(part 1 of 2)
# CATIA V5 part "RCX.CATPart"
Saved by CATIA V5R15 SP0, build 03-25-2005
Part number: Part1
Material "DS Yellow": density 7860 kg/m3, Young's modulus 2e+11 Pa, Poisson ratio 0.266
Material "Black": density 7860 kg/m3, Young's modulus 2e+11 Pa, Poisson ratio 0.266
Material "Purple Grey": density 7860 kg/m3, Young's modulus 2e+11 Pa, Poisson ratio 0.266
Material "Fire Red": density 7860 kg/m3, Young's modulus 2e+11 Pa, Poisson ratio 0.266
Material "Black": density 7860 kg/m3, Young's modulus 2e+11 Pa, Poisson ratio 0.266
Material "Silver Grey": density 7860 kg/m3, Young's modulus 2e+11 Pa, Poisson ratio 0.266
Material "DS Green": density 7860 kg/m3, Young's modulus 2e+11 Pa, Poisson ratio 0.266
Material "Dark Grey": density 7860 kg/m3, Young's modulus 2e+11 Pa, Poisson ratio 0.266
Material "Bathroom Floor": density 2770 kg/m3, Young's modulus 6e+10 Pa, Poisson ratio 0.3
Material "Plastic": density 1200 kg/m3, Young's modulus 2.2e+09 Pa, Poisson ratio 0.38, thermal expansion 6.84e-05 1/K
Bounding box of the stored display mesh (mm): x -320 to 320, y -3 to 960, z 0 to 397.2
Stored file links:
  E:\#01 CATIA Lecture Materials\#06 DMU\#11 DMU Page01 KIN EX11\RCX.CATPart
  C:\Program Files\Dassault Systemes\B20\win_b64\startup\materials\Catalog.CATMaterial
  C:\Program Files\Dassault Systemes\B20\win_b64\startup\materials\yellow_env_512x512.jpg
  C:\Program Files\Dassault Systemes\B20\win_b64\startup\materials\green_env_512x512.jpg
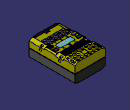
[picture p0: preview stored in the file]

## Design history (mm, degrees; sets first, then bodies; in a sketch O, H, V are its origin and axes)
Body1 (main body), material "DS Yellow"
  Sketch1 on xy-plane, origin (0, 0, 0), H (1, 0, 0), V (0, 1, 0)
    point P1 (320, 0)
    line L1 (320, 0) -> (320, 960)
    line L2 (320, 960) -> (-320, 960)
    line L3 (-320, 960) -> (-320, 0)
    point P4 (-320, 0)
    line L4 (-320, 0) -> (320, 0)
    length L1 = 960
    distance L1 L3 = 640
    coincidence: P1 H, P4 H
    vertical: L1 V, L3 V
    horizontal: L2 H, L4 H
    symmetry: L1 L3 V
  Pad1: profile Sketch1, direction (0, 0, 1), length 380
  Sketch2 on face of Pad1 from Sketch1.L4, origin (0, 0, 0), H (1, 0, 0), V (0, 0, 1)
    point P1 (245, 380)
    line L1 (245, 380) -> (320, 380)
    point P2 (320, 380)
    line L2 (320, 380) -> (320, 345)
    point P3 (320, 345)
    line L3 (320, 345) -> (245, 380)
    reference projected line E1 (320, 0) -> (320, 380) from edge [face of Pad1 from Sketch1.L1 | face of Pad1 from Sketch1.L4]
    reference projected line E2 (-320, 380) -> (320, 380) from edge [face of Pad1 from Sketch1.L4 | end face of Pad1]
    point P4 (-245, 380)
    point P5 (-320, 380)
    point P6 (-320, 345)
    line L4 (-245, 380) -> (-320, 380)
    line L5 (-320, 380) -> (-320, 345)
    line L6 (-320, 345) -> (-245, 380)
    length L2 = 35
    length L1 = 75
    horizontal: L1 H
    vertical: L2 V
    coincidence: L2 E1, L1 E2
    symmetry: P1 P4 V, P2 P5 V, P3 P6 V, L1 L4 V, L2 L5 V, L3 L6 V
  Pocket1: profile Sketch2, direction (0, 1, 0), through (limit type 6)
  Sketch3 on face of Pad1 from Sketch1.L4, origin (0, 0, 0), H (1, 0, 0), V (0, 0, 1)
    line L1 (-320, 380) -> (320, 380)
    line L2 (320, 380) -> (320, 350)
    line L3 (320, 350) -> (-320, 350)
    line L4 (-320, 350) -> (-320, 380)
    reference projected line E1 (-320, 380) -> (320, 380) from edge [face of Pad1 from Sketch1.L4 | end face of Pad1]
    reference projected line E2 (320, 0) -> (320, 380) from edge [face of Pad1 from Sketch1.L1 | face of Pad1 from Sketch1.L4]
    reference projected line E3 (-320, 0) -> (-320, 380) from edge [face of Pad1 from Sketch1.L4 | face of Pad1 from Sketch1.L3]
    distance L3 L1 = 30
    horizontal: L1 H, L3 H
    vertical: L2 V, L4 V
    coincidence: L1 E1, L2 E2, L4 E3
  Pocket2: profile Sketch3, direction (0, 1, 0), length 720
  Sketch4 on face of Pad1 from Sketch1.L4, origin (0, 0, 0), H (1, 0, 0), V (0, 0, 1)
    point P1 (245, 350)
    line L1 (245, 350) -> (320, 350)
    point P2 (320, 350)
    line L2 (320, 350) -> (320, 315)
    point P3 (320, 315)
    line L3 (320, 315) -> (245, 350)
    reference projected line E1 (-309.2857, 350) -> (309.2857, 350) from edge [face of Pad1 from Sketch1.L4 | face of Pocket2 from Sketch3.L3]
    reference projected line E2 (320, 0) -> (320, 380) from edge [face of Pad1 from Sketch1.L1 | face of Pad1 from Sketch1.L4]
    point P4 (-245, 350)
    point P5 (-320, 350)
    point P6 (-320, 315)
    line L4 (-245, 350) -> (-320, 350)
    line L5 (-320, 350) -> (-320, 315)
    line L6 (-320, 315) -> (-245, 350)
    length L2 = 35
    length L1 = 75
    horizontal: L1 H
    vertical: L2 V
    coincidence: L1 E1, L2 E2
    symmetry: P1 P4 V, P2 P5 V, P3 P6 V, L1 L4 V, L2 L5 V, L3 L6 V
  Pocket3: profile Sketch4, direction (0, 1, 0), length 320
  Sketch5 on face of Pad1 from Sketch1.L4, origin (0, 0, 0), H (1, 0, 0), V (0, 0, 1)
    point P1 (245, 350)
    line L1 (245, 350) -> (320, 350)
    point P2 (320, 350)
    line L2 (320, 350) -> (320, 315)
    point P3 (320, 315)
    line L3 (320, 315) -> (245, 350)
    reference projected line E1 (-309.2857, 350) -> (309.2857, 350) from edge [face of Pad1 from Sketch1.L4 | face of Pocket2 from Sketch3.L3]
    reference projected line E2 (320, 0) -> (320, 380) from edge [face of Pad1 from Sketch1.L1 | face of Pad1 from Sketch1.L4]
    point P4 (-245, 350)
    point P5 (-320, 350)
    point P6 (-320, 315)
    line L4 (-245, 350) -> (-320, 350)
    line L5 (-320, 350) -> (-320, 315)
    line L6 (-320, 315) -> (-245, 350)
    length L2 = 35
    length L1 = 75
    horizontal: L1 H
    vertical: L2 V
    coincidence: L1 E1, L2 E2
    symmetry: P1 P4 V, P2 P5 V, P3 P6 V, L1 L4 V, L2 L5 V, L3 L6 V
  Pocket4: profile Sketch5, direction (0, 1, 0), length 720, opposite side length -550
  Sketch6 on end face of Pocket3, origin (0, 320, 0), H (1, 0, 0), V (0, 0, 1)
    point P1 (320, 335)
    line L1 (320, 335) -> (320, 350)
    point P2 (320, 350)
    line L2 (320, 350) -> (290, 350)
    point P3 (290, 350)
    line L3 (290, 350) -> (320, 335)
    reference projected line E1 (-245, 350) -> (-309.2857, 350) from edge [face of Pocket2 from Sketch3.L3 | end face of Pocket3]
    reference projected line E3 (320, 315) -> (320, 345) from edge [face of Pad1 from Sketch1.L1 | end face of Pocket3]
    point P4 (-320, 335)
    point P5 (-320, 350)
    point P6 (-290, 350)
    line L4 (-320, 335) -> (-320, 350)
    line L5 (-320, 350) -> (-290, 350)
    line L6 (-290, 350) -> (-320, 335)
    length L2 = 30
    length L1 = 15
    vertical: L1 V
    horizontal: L2 H
    coincidence: L2 E1, L1 E3
    symmetry: P1 P4 V, P2 P5 V, P3 P6 V, L1 L4 V, L2 L5 V, L3 L6 V
  Pocket5: profile Sketch6, direction (0, 1, 0), length 230
  Sketch7 on face of Pocket2 from Sketch3.L3, origin (0, 0, 350), H (1, 0, 0), V (0, 1, 0)
    line L1 (-237, 720) -> (237, 720)
    line L2 (237, 720) -> (237, 562)
    line L3 (237, 562) -> (-237, 562)
    line L4 (-237, 562) -> (-237, 720)
    reference projected line E1 (320, 720) -> (-320, 720) from edge [face of Pocket2 from Sketch3.L3 | face of Pocket4]
    line L5 (237, 162) -> (-237, 162)
    line L6 (237, 320) -> (237, 162)
    line L7 (-237, 320) -> (237, 320)
    line L8 (-237, 162) -> (-237, 320)
    reference projected line E2 (-245, 320) -> (-309.2857, 320) from edge [face of Pocket2 from Sketch3.L3 | end face of Pocket3]
    length L2 = 158
    distance L2 L4 = 474
    distance L5 L7 = 158
    distance L6 L8 = 474
    horizontal: L1 H, L3 H
    vertical: L2 V, L4 V
    coincidence: L1 E1, L7 E2
    symmetry: L2 L4 V, L6 L8 V
  Pocket6: profile Sketch7, direction (0, 0, -1), length 32
  Sketch8 on face of Pad1 from Sketch1.L2, origin (0, 960, 0), H (-1, 0, 0), V (0, 0, 1)
    point P1 (-320, 190)
    line L1 (-320, 190) -> (320, 190)
    point P2 (320, 190)
    reference projected line E1 (-320, 380) -> (320, 380) from edge [face of Pad1 from Sketch1.L2 | end face of Pad1]
    reference projected line E2 (320, 0) -> (320, 380) from edge [face of Pad1 from Sketch1.L3 | face of Pad1 from Sketch1.L2]
    reference projected line E3 (-320, 0) -> (-320, 380) from edge [face of Pad1 from Sketch1.L2 | face of Pad1 from Sketch1.L1]
    distance L1 E1 = 190
    horizontal: L1 H
    coincidence: P2 E2, P1 E3
  Pocket7: profile Sketch8, direction (0, -1, 0), length 5, thin wall 5, second thickness 5
  Sketch9 on face of Pad1 from Sketch1.L3, origin (-320, 0, 0), H (0, -1, 0), V (0, 0, 1)
    point P1 (-960, 190)
    line L1 (-960, 190) -> (0, 190)
    point P2 (0, 190)
    reference projected line E1 (-960, 0) -> (-960, 380) from edge [face of Pad1 from Sketch1.L3 | face of Pad1 from Sketch1.L2]
    reference projected line E2 (0, 380) -> (-960, 380) from edge [end face of Pad1 | face of Pocket1 from Sketch2.L6]
    reference projected line E3 (0, 0) -> (0, 380) from edge [face of Pad1 from Sketch1.L4 | face of Pad1 from Sketch1.L3]
    distance L1 E2 = 190
    horizontal: L1 H
    coincidence: P1 E1, P2 E3
  Pocket8: profile Sketch9, direction (1, 0, 0), length 5, thin wall 5, second thickness 5
  Sketch10 on face of Pad1 from Sketch1.L4, origin (0, 0, 0), H (1, 0, 0), V (0, 0, 1)
    point P1 (-320, 190)
    line L1 (-320, 190) -> (320, 190)
    point P2 (320, 190)
    reference projected line E1 (245, 380) -> (-245, 380) from edge [end face of Pad1 | face of Pocket4]
    reference projected line E2 (-320, 0) -> (-320, 380) from edge [face of Pad1 from Sketch1.L4 | face of Pad1 from Sketch1.L3]
    reference projected line E3 (320, 0) -> (320, 380) from edge [face of Pad1 from Sketch1.L1 | face of Pad1 from Sketch1.L4]
    distance E1 L1 = 190
    horizontal: L1 H
    coincidence: P1 E2, P2 E3
  Pocket9: profile Sketch10, direction (0, 1, 0), length 5, thin wall 5, second thickness 5
  Sketch11 on face of Pad1 from Sketch1.L1, origin (320, 0, 0), H (0, 1, 0), V (0, 0, 1)
    point P1 (0, 190)
    line L1 (0, 190) -> (960, 190)
    point P2 (960, 190)
    reference projected line E1 (960, 0) -> (960, 380) from edge [face of Pad1 from Sketch1.L2 | face of Pad1 from Sketch1.L1]
    reference projected line E2 (0, 0) -> (0, 380) from edge [face of Pad1 from Sketch1.L1 | face of Pad1 from Sketch1.L4]
    reference projected line E3 (0, 380) -> (960, 380) from edge [face of Pocket1 from Sketch2.L3 | end face of Pad1]
    distance L1 E3 = 190
    horizontal: L1 H
    coincidence: P2 E1, P1 E2
  Pocket10: profile Sketch11, direction (-1, 0, 0), length 5, thin wall 5, second thickness 5
  Sketch12 on face of Pad1 from Sketch1.L4, origin (0, 0, 0), H (1, 0, 0), V (0, 0, 1)
    point P1 (320, 0)
    line L1 (320, 0) -> (-320, 0)
    line L2 (-320, 0) -> (-320, 185)
    line L3 (-320, 185) -> (320, 185)
    line L4 (320, 185) -> (320, 0)
    reference projected line E1 (-320, 185) -> (-315, 185) from edge [face of Pad1 from Sketch1.L4 | face of Pocket10]
    reference projected line E2 (320, 0) -> (320, 380) from edge [face of Pad1 from Sketch1.L1 | face of Pad1 from Sketch1.L4]
    reference projected line E3 (-320, 0) -> (-320, 380) from edge [face of Pad1 from Sketch1.L4 | face of Pad1 from Sketch1.L3]
    coincidence: P1 H, E1 L3, E2 L4, L2 E3
    horizontal: L1 H, L3 H
    vertical: L2 V, L4 V
  Pocket11: profile Sketch12, direction (0, 1, 0), through (limit type 6)
  Sketch13 on face of Pocket2 from Sketch3.L3, origin (0, 0, 350), H (1, 0, 0), V (0, 1, 0)
    line L1 (-160, 485) -> (-160, 385)
    arc A1 centre (0, 1660) radius 1285 from (-160, 385) to (160, 385) ccw
    point P4 (0, 375)
    line L2 (160, 385) -> (160, 485)
    arc A2 centre (0, -790) radius 1285 from (160, 485) to (-160, 485) ccw
    point P8 (0, 495)
    axis line L3 (534.9151, 435) -> (-283.043, 435)
    reference projected line E1 (-245, 320) -> (-309.2857, 320) from edge [face of Pocket2 from Sketch3.L3 | end face of Pocket3]
    length L2 = 100
    length L1 = 100
    distance L2 L1 = 320
    distance L3 E1 = 115
    distance A2 A1 = 120
    vertical: L1 V, L2 V
    coincidence: A1 P4, P4 V, A2 P8, P8 V
    symmetry: L1 L2 V, A1 A2 L3
    horizontal: L3 H
  Pocket12: profile Sketch13, direction (0, 0, -1), length 30
  Sketch14 on face of Pocket2 from Sketch3.L3, origin (0, 0, 350), H (1, 0, 0), V (0, 1, 0)
    point P1 (200, 507.5)
    line L1 (200, 507.5) -> (200, 472.5)
    point P2 (200, 472.5)
    arc A1 centre (240, 630) radius 162.5 from (200, 472.5) to (280, 472.5) ccw
    point P3 (240, 630)
    point P4 (280, 472.5)
    line L2 (280, 472.5) -> (280, 507.5)
    point P5 (280, 507.5)
    arc A2 centre (240, 350) radius 162.5 from (280, 507.5) to (200, 507.5) ccw
    point P6 (240, 350)
    construction line L3 (240, 533.7605) -> (240, 386.1992)
    point P7 (240, 533.7605)
    reference projected line E1 (320, 320) -> (320, 550) from edge [face of Pad1 from Sketch1.L1 | face of Pocket5 from Sketch6.L3]
    construction line L4 (152.5705, 490) -> (327.5235, 490)
    point P9 (152.5705, 490)
    point P10 (327.5235, 490)
    reference projected line E2 (-245, 550) -> (-309.2857, 550) from edge [start face of Pocket4 | face of Pocket2 from Sketch3.L3]
    construction line L5 (479.259, 435) -> (35.5084, 435)
    reference projected line E4 (-245, 320) -> (-309.2857, 320) from edge [face of Pocket2 from Sketch3.L3 | end face of Pocket3]
    point P13 (200, 362.5)
    point P14 (200, 397.5)
    point P15 (280, 397.5)
    point P16 (280, 362.5)
    point P17 (240, 336.2395)
    point P18 (152.5705, 380)
    point P19 (327.5235, 380)
    construction line L6 (152.5705, 380) -> (327.5235, 380)
    line L7 (200, 362.5) -> (200, 397.5)
    arc A3 centre (240, 240) radius 162.5 from (200, 397.5) to (280, 397.5) cw
    line L8 (280, 397.5) -> (280, 362.5)
    point P21 (240, 520)
    arc A4 centre (240, 520) radius 162.5 from (280, 362.5) to (200, 362.5) cw
    point P22 (-200, 507.5)
    point P23 (-200, 472.5)
    point P24 (-280, 472.5)
    point P25 (-280, 507.5)
    point P26 (-240, 533.7605)
    point P27 (-327.5235, 490)
    point P28 (-240, 520)
    line L9 (-200, 507.5) -> (-200, 472.5)
    arc A5 centre (-240, 630) radius 162.5 from (-200, 472.5) to (-280, 472.5) cw
    line L10 (-280, 472.5) -> (-280, 507.5)
    arc A6 centre (-240, 350) radius 162.5 from (-280, 507.5) to (-200, 507.5) cw
    arc A7 centre (-240, 520) radius 162.5 from (-280, 362.5) to (-200, 362.5) ccw
    arc A8 centre (-240, 240) radius 162.5 from (-200, 397.5) to (-280, 397.5) ccw
    line L11 (-200, 362.5) -> (-200, 397.5)
    line L12 (-280, 397.5) -> (-280, 362.5)
    construction line L13 (-240, 419.4533) -> (-240, 336.2395)
    reference projected line E6 (-320, 0) -> (-320, 320) from edge [face of Pocket3 from Sketch4.L6 | face of Pad1 from Sketch1.L3]
    axis line L14 (-343.1113, 380) -> (-157.5, 380)
    point P39 (-157.5, 380)
    distance L3 E1 = 80
    distance L2 L1 = 80
    distance A2 A1 = 45
    distance L4 E2 = 60
    length L2 = 35
    distance L5 E4 = 115
    distance L12 L11 = 80
    distance A8 A7 = 45
    distance L13 E6 = 80
    length L12 = 35
    length L11 = 35
    vertical: L1 V, L2 V, L3 V, L13 V
    coincidence: P3 L3, P6 L3, P39 A7
    symmetry: L2 L1 L3, A1 A2 L4, P1 P13 L5, P2 P14 L5, P4 P15 L5, P5 P16 L5, P7 P17 L5, P9 P18 L5, P10 P19 L5, L4 L6 L5, L1 L7 L5, A1 A3 L5, L2 L8 L5, A2 A4 L5, P1 P22 V, P2 P23 V, P4 P24 V, P5 P25 V, P7 P26 V, P10 P27 V, P21 P28 V, L1 L9 V, A1 A5 V, L2 L10 V, A2 A6 V, A8 A7 L6, L12 L11 L13, A8 A7 L14
    horizontal: L4 H, L5 H, L14 H
  Pocket13: profile Sketch14, direction (0, 0, -1), length 30
  Sketch15 on face of Pocket2 from Sketch3.L3, origin (0, 0, 350), H (1, 0, 0), V (0, 1, 0)
    point P1 (237.5, 0)
    line L1 (237.5, 0) -> (237.5, 40)
    line L2 (237.5, 40) -> (40, 40)
    line L3 (40, 40) -> (40, 80)
    line L4 (40, 80) -> (-40, 80)
    line L5 (-40, 80) -> (-40, 40)
    point P6 (-40, 40)
    line L6 (-40, 40) -> (-237.5, 40)
    line L7 (-237.5, 40) -> (-237.5, 0)
    point P8 (-237.5, 0)
    line L8 (-237.5, 0) -> (237.5, 0)
    distance L3 L5 = 80
    distance L2 L8 = 40
    distance L4 L8 = 80
    distance L1 L7 = 475
    coincidence: P1 H, P6 L2, P8 H
    vertical: L1 V, L3 V, L5 V, L7 V
    horizontal: L2 H, L4 H, L6 H, L8 H
    symmetry: L3 L5 V, L1 L7 V
  Pocket14: profile Sketch15, direction (0, 0, -1), length 155
  Sketch16 on end face of Pad1, origin (0, 0, 380), H (1, 0, 0), V (0, 1, 0)
    circle A1 centre (205.5, 920.5) radius 24.5
    point P1 (205.5, 920.5)
    reference projected line E1 (320, 960) -> (-320, 960) from edge [face of Pad1 from Sketch1.L2 | end face of Pad1]
    reference projected line E2 (245, 0) -> (245, 960) from edge [face of Pocket1 from Sketch2.L3 | end face of Pad1]
    radius A1 = 24.5
    distance P1 E1 = 39.5
    distance P1 E2 = 39.5
  Pad2: profile Sketch16, direction (0, 0, 1), length 17.2
  RectPattern1: of Pad2, direction 1 instances 6, spacing 79, along end face of Pad1 reversed, direction 2 instances 3, spacing 79, along end face of Pad1 reversed
  Sketch17 on face of RectPattern1, origin (0, 0, 397.2), H (1, 0, 0), V (0, 1, 0)
    line L1 (-75, 870) -> (75, 870)
    line L2 (75, 870) -> (75, 810)
    line L3 (75, 810) -> (-75, 810)
    line L4 (-75, 810) -> (-75, 870)
    reference projected line E1 (245, 720) -> (-245, 720) from edge [end face of Pad1 | face of Pocket4]
    distance L2 L4 = 150
    distance L1 L3 = 60
    distance L3 E1 = 90
    horizontal: L1 H, L3 H
    vertical: L2 V, L4 V
    symmetry: L2 L4 V
  Pocket15: profile Sketch17, direction (0, 0, -1), length 17.2
  Sketch18 on face of Pocket15, origin (0, 0, 380), H (1, 0, 0), V (0, 1, 0)
    line L1 (-47.5, 885) -> (47.5, 885)
    line L2 (47.5, 885) -> (47.5, 795)
    line L3 (47.5, 795) -> (-47.5, 795)
    line L4 (-47.5, 795) -> (-47.5, 885)
    reference projected line E1 (245, 720) -> (-245, 720) from edge [end face of Pad1 | face of Pocket4]
    distance L3 E1 = 75
    distance L1 L3 = 90
    distance L4 L2 = 95
    horizontal: L1 H, L3 H
    vertical: L2 V, L4 V
    symmetry: L2 L4 V
  Pocket16: profile Sketch18, direction (0, 0, -1), length 5
  Sketch19 on face of Pad1 from Sketch1.L1, origin (320, 0, 0), H (0, 1, 0), V (0, 0, 1)
    circle A1 centre (235, 270) radius 24.5
    point P1 (235, 270)
    circle A2 centre (640, 270) radius 24.5
    point P2 (640, 270)
    reference projected line E1 (960, 0) -> (960, 380) from edge [face of Pad1 from Sketch1.L2 | face of Pad1 from Sketch1.L1]
    reference projected line E2 (0, 380) -> (960, 380) from edge [face of Pocket1 from Sketch2.L3 | face of Pocket15]
    reference projected line E3 (0, 380) -> (960, 380) from edge [face of Pocket1 from Sketch2.L3 | face of Pocket15]
    radius A2 = 24.5
    radius A1 = 24.5
    distance E1 P2 = 320
    distance P2 E2 = 110
    distance P1 E3 = 110
    distance P1 V = 235
  Pocket17: profile Sketch19, direction (-1, 0, 0), length 50
  Mirror1: of Pocket17, about yz-plane
  Sketch20 on face of Pocket2 from Sketch3.L3, origin (0, 0, 350), H (1, 0, 0), V (0, 1, 0)
    point P1 (270, 259.5)
    line L1 (270, 259.5) -> (305, 259.5)
    line L2 (305, 259.5) -> (305, 210.5)
    line L3 (305, 210.5) -> (270, 210.5)
    line L4 (270, 210.5) -> (270, 259.5)
    point P2 (305, 259.5)
    point P3 (305, 210.5)
    point P4 (270, 210.5)
    reference projected line E1 (320, 0) -> (320, 320) from edge [face of Pad1 from Sketch1.L1 | face of Pocket3 from Sketch4.L3]
    construction line L5 (453.9591, 235) -> (-363.6449, 235)
    point P7 (-270, 210.5)
    point P8 (-270, 259.5)
    line L6 (-270, 259.5) -> (-270, 210.5)
    point P9 (-305, 210.5)
    line L7 (-270, 210.5) -> (-305, 210.5)
    point P10 (-305, 259.5)
    line L8 (-305, 210.5) -> (-305, 259.5)
    line L9 (-305, 259.5) -> (-270, 259.5)
    reference projected line E2 (-320, 0) -> (-320, 320) from edge [face of Pocket3 from Sketch4.L6 | face of Pad1 from Sketch1.L3]
    axis line L10 (453.9591, 437.5) -> (-407.2692, 437.5)
    point P13 (270, 615.5)
    point P14 (305, 615.5)
    point P15 (305, 664.5)
    point P16 (270, 664.5)
    point P17 (-270, 664.5)
    point P18 (-270, 615.5)
    point P19 (-305, 664.5)
    point P20 (-305, 615.5)
    line L11 (270, 615.5) -> (305, 615.5)
    line L12 (305, 615.5) -> (305, 664.5)
    line L13 (305, 664.5) -> (270, 664.5)
    line L14 (270, 664.5) -> (270, 615.5)
    line L15 (-270, 615.5) -> (-270, 664.5)
    line L16 (-270, 664.5) -> (-305, 664.5)
    line L17 (-305, 664.5) -> (-305, 615.5)
    line L18 (-305, 615.5) -> (-270, 615.5)
    distance L1 L3 = 49
    distance L2 E1 = 15
    distance L5 H = 235
    distance L4 L2 = 35
    distance L8 E2 = 15
    distance L6 L8 = 35
    distance L9 L7 = 49
    distance L10 L5 = 202.5
    horizontal: L1 H, L3 H, L5 H, L10 H
    vertical: L2 V, L4 V
    symmetry: L3 L1 L5, L7 L9 L5, P1 P13 L10, P2 P14 L10, P3 P15 L10, P4 P16 L10, P7 P17 L10, P8 P18 L10, P9 P19 L10, P10 P20 L10, L1 L11 L10, L2 L12 L10, L3 L13 L10, L4 L14 L10, L6 L15 L10, L7 L16 L10, L8 L17 L10, L9 L18 L10
  Pocket18: profile Sketch20, direction (0, 0, -1), length 50
  Sketch21 on face of Pocket1 from Sketch2.L3, origin (189.4343, 0, 405.9307), H (0, 1, 0), V (-0.9062, 0, 0.4229)
    construction line L1 (737.037, -84.0831) -> (944.0219, -84.0831)
    axis line L2 (737.037, -124.0831) -> (944.0219, -124.0831)
    reference projected line E1 (0, -144.0831) -> (960, -144.0831) from edge [face of Pad1 from Sketch1.L1 | face of Pocket1 from Sketch2.L3]
    point P5 (752.4866, -84.0831)
    line L3 (752.4866, -84.0831) -> (752.4866, -124.0831)
    point P6 (752.4866, -124.0831)
    line L4 (752.4866, -84.0831) -> (770.028, -84.0831)
    arc A1 centre (770.028, -94.3286) radius 10.2455 from (770.028, -84.0831) to (770.028, -104.574) cw
    point P9 (770.028, -104.574)
    point P10 (752.4866, -104.0831)
    point P11 (770.028, -104.574)
    line L5 (770.028, -104.574) -> (752.4866, -104.574)
    point P12 (752.4866, -104.574)
    line L6 (770.028, -104.574) -> (778.5158, -124.0831)
    point P13 (778.5158, -124.0831)
    point P14 (819.2571, -124.0831)
    line L7 (819.2571, -124.0831) -> (802.8474, -124.0831)
    arc A2 centre (802.8474, -104.0831) radius 20 from (802.8474, -124.0831) to (802.8474, -84.0831) cw
    line L8 (802.8474, -84.0831) -> (819.2571, -84.0831)
    point P19 (828.8765, -124.0831)
    line L9 (828.8765, -124.0831) -> (858.3008, -84.0831)
    point P20 (858.3008, -84.0831)
    point P21 (828.8765, -84.0831)
    line L10 (828.8765, -84.0831) -> (858.3008, -124.0831)
    point P22 (858.3008, -124.0831)
    arc A3 centre (883.1982, -95.0783) radius 10.9951 from (872.2287, -94.3286) to (893.808, -97.9638) cw
    point P25 (883.1982, -84.0831)
    line L11 (893.808, -97.9638) -> (872.2287, -124.0831)
    point P27 (872.2287, -124.0831)
    line L12 (872.2287, -124.0831) -> (893.808, -124.0831)
    construction line L13 (919.2866, -94.0421) -> (919.2866, -114.1242)
    line L14 (929.2456, -94.0421) -> (929.2456, -114.1242)
    line L15 (909.3277, -114.1242) -> (909.3277, -94.0421)
    arc A4 centre (919.2866, -114.1242) radius 9.959 from (929.2456, -114.1242) to (909.3277, -114.1242) cw
    arc A5 centre (919.2866, -94.0421) radius 9.959 from (909.3277, -94.0421) to (929.2456, -94.0421) cw
    circle A6 centre (901.4076, -124.0831) radius 0.8459
    point P35 (901.4076, -124.0831)
    point P36 (902.2535, -124.0831)
    distance L1 L2 = 40
    distance L2 E1 = 20
    distance A5 A4 = 40
    horizontal: L1 H, L2 H, L4 H, L7 H
    coincidence: P5 L1, P6 L2, P11 A1, P12 L3, P13 L2, P14 L2, P19 L2, P20 L1, P21 L1, P22 L2, A3 P25, P25 L1, P27 L2, P9 P11, P35 L2, A6 P36, P36 L2
    vertical: L3 V, L13 V
    tangency: A1 L4, L5 A1, A2 L1, A2 L7, L8 A2, A3 L1, L12 A2, A4 L14, A5 L14, A4 L15, A5 L15, A4 L2
    midpoint: P10 L3
    parallelism: L13 L14
  Pocket19: profile Sketch21, direction (-0.4229, 0, -0.9062), length 30, thin wall 1, second thickness 1
  Sketch22 on face of Pocket1 from Sketch2.L6, origin (-189.4343, 0, 405.9307), H (0, -1, 0), V (0.9062, 0, 0.4229)
    construction line L1 (-929.1943, -84.0831) -> (-750.0494, -84.0831)
    axis line L2 (-931.739, -114.0831) -> (-750.0494, -114.0831)
    reference projected line E1 (-720, -144.0831) -> (-960, -144.0831) from edge [face of Pocket1 from Sketch2.L6 | face of Pad1 from Sketch1.L3]
    point P5 (-923.596, -84.0831)
    line L3 (-923.596, -84.0831) -> (-907.819, -84.0831)
    arc A1 centre (-871.3639, -111.6138) radius 45.6828 from (-907.819, -84.0831) to (-916.9799, -114.0831) ccw
    point P7 (-916.9799, -114.0831)
    arc A2 centre (-886.6141, -89.3776) radius 5.95 from (-892.551, -88.9837) to (-884.917, -95.0805) cw
    point P10 (-883.8991, -84.0831)
    arc A3 centre (-888.6692, -104.2114) radius 9.8718 from (-884.917, -95.0805) to (-888.6692, -114.0831) cw
    point P13 (-888.6692, -114.0831)
    arc A4 centre (-888.6692, -104.2114) radius 9.8718 from (-888.6692, -114.0831) to (-898.541, -104.2114) cw
    point P15 (-897.2207, -109.1433)
    circle A5 centre (-860.9971, -89.3776) radius 5.2945
    circle A6 centre (-860.9971, -104.2114) radius 9.8718
    point P19 (-827.4074, -84.0831)
    line L4 (-827.4074, -84.0831) -> (-839.6219, -84.0831)
    point P20 (-839.6219, -84.0831)
    line L5 (-839.6219, -84.0831) -> (-843.0289, -95.0805)
    arc A7 centre (-836.9408, -103.6065) radius 10.4766 from (-843.0289, -95.0805) to (-826.4748, -103.1353) cw
    point P23 (-826.4748, -103.1353)
    arc A8 centre (-836.9408, -103.6065) radius 10.4766 from (-826.4748, -103.1353) to (-847.1559, -105.9324) cw
    point P25 (-828.0467, -109.1433)
    construction line L6 (-805.2386, -92.1618) -> (-805.2386, -106.7434)
    line L7 (-797.5294, -92.1618) -> (-797.5294, -106.7434)
    line L8 (-812.9479, -106.7434) -> (-812.9479, -92.1618)
    arc A9 centre (-805.2386, -106.7434) radius 7.7092 from (-797.5294, -106.7434) to (-812.9479, -106.7434) cw
    arc A10 centre (-805.2386, -92.1618) radius 7.7092 from (-812.9479, -92.1618) to (-797.5294, -92.1618) cw
    arc A11 centre (-778.5605, -89.4277) radius 5.95 from (-784.4974, -89.0338) to (-776.8634, -95.1306) cw
    arc A12 centre (-780.6156, -104.2614) radius 9.8718 from (-776.8634, -95.1306) to (-780.6156, -114.1332) cw
    arc A13 centre (-780.6156, -104.2614) radius 9.8718 from (-780.6156, -114.1332) to (-790.4874, -104.2614) cw
    distance L2 E1 = 30
    distance L1 L2 = 30
    distance A10 A9 = 30
    horizontal: L1 H, L2 H, L3 H
    coincidence: P5 L1, P7 L2, A2 P10, P10 L1, P13 L2, A4 P15, P15 A3, P19 L1, P23 A1, A8 P25, P25 A7
    tangency: A3 L2, A4 L2, A5 L1, A6 L2, L4 A5, A7 L2, A8 L2, A9 L7, A10 L7, A9 L8, A10 L8
    midpoint: P20 L1
    vertical: L6 V
    parallelism: L6 L7
  Pocket20: profile Sketch22, direction (0.4229, 0, -0.9062), length 5, thin wall 1, second thickness 1
  Sketch23 on face of Pocket2 from Sketch3.L3, origin (0, 0, 350), H (1, 0, 0), V (0, 1, 0)
    line L1 (112.6795, 325.1406) -> (112.6795, 368.8716)
    construction line L2 (156.8704, 324.796) -> (-165.4748, 324.796)
    construction line L3 (168.5857, 368.5269) -> (-170.4339, 368.5269)
    point P5 (168.5857, 368.5269)
    arc A1 centre (-4.3022, 334.1591) radius 9.3631 from (4.7096, 336.6998) to (-13.314, 336.6998) cw
    point P9 (-4.3022, 324.796)
    line L4 (-13.314, 336.6998) -> (4.7096, 368.5269)
    point P11 (4.7096, 368.5269)
    line L5 (4.7096, 368.5269) -> (-13.314, 368.5269)
    arc A2 centre (-121.7599, 334.0429) radius 9.6835 from (-112.0771, 334.1591) to (-129.8831, 339.3139) cw
    point P15 (-118.8853, 324.796)
    line L6 (-129.8831, 339.3139) -> (-127.6869, 342.6986)
    arc A3 centre (-120.7532, 354.6821) radius 13.8448 from (-127.6869, 342.6986) to (-107.2284, 357.6419) cw
    construction line L7 (151.8168, 505.6692) -> (-165.4748, 505.6692)
    construction line L8 (151.8168, 549) -> (-172.9693, 549)
    point P24 (114.8981, 505.6692)
    line L9 (114.8981, 505.6692) -> (134.8538, 549)
    point P25 (134.8538, 549)
    line L10 (114.8981, 505.6692) -> (97.9352, 549)
    point P26 (97.9352, 549)
    point P27 (126.2951, 530.416)
    line L11 (126.2951, 530.416) -> (105.2104, 530.416)
    point P28 (105.2104, 530.416)
    point P29 (1.6469, 505.6692)
    line L12 (1.6469, 505.6692) -> (1.6469, 549)
    point P30 (1.6469, 549)
    line L13 (1.6469, 505.6692) -> (-15.6405, 505.6692)
    arc A4 centre (-15.6405, 513.9682) radius 8.2989 from (-15.6405, 505.6692) to (-15.6405, 522.2671) cw
    point P33 (-15.6405, 522.2671)
    line L14 (-15.6405, 522.2671) -> (1.6469, 522.2671)
    point P34 (1.6469, 522.2671)
    point P35 (-15.6405, 522.2671)
    arc A5 centre (-10.235, 536.1232) radius 14.8732 from (-15.6405, 522.2671) to (-17.6781, 549) cw
    point P37 (-17.6781, 549)
    line L15 (-17.6781, 549) -> (1.6469, 549)
    point P38 (-124.6248, 505.6692)
    arc A6 centre (-124.6248, 527.3346) radius 21.6654 from (-124.6248, 505.6692) to (-124.6248, 549) ccw
    point P40 (-124.6248, 549)
    line L16 (-124.6248, 505.6692) -> (-135.1884, 505.6692)
    line L17 (-124.6248, 549) -> (-136.893, 549)
    axis line L18 (394.3199, 437) -> (-265.8141, 437)
    reference projected line E1 (-245, 320) -> (-309.2857, 320) from edge [face of Pocket2 from Sketch3.L3 | end face of Pocket3]
    distance E1 L18 = 117
    vertical: L1 V, L12 V
    horizontal: L2 H, L3 H, L5 H, L7 H, L8 H, L11 H, L13 H, L15 H, L18 H
    coincidence: A1 P9, P11 L3, A2 P15, P15 L2, P24 L7, P25 L8, P26 L8, L10 P5, P27 L9, P28 L10, P29 L7, P30 L8, P34 L12, P37 L8, P38 L7, P40 L8, P33 P35
    midpoint: P9 L2
    tangency: A1 L2, L6 A2, A3 L5, A4 L13, L14 A4, A6 L8, L16 A6, L17 A6
  Pocket21: profile Sketch23, direction (0, 0, -1), length 5, thin wall 1, second thickness 1
  Sketch24 on face of Pocket2 from Sketch3.L3, origin (0, 0, 350), H (1, 0, 0), V (0, 1, 0)
    construction line L1 (280.2742, 354.5796) -> (202.181, 354.5796)
    construction line L2 (279.9343, 323.4137) -> (201.8411, 323.4137)
    point P5 (277.9777, 323.4137)
    line L3 (277.9777, 323.4137) -> (268.1291, 354.5796)
    point P6 (268.1291, 354.5796)
    line L4 (268.1291, 354.5796) -> (257.0981, 323.4137)
    point P7 (257.0981, 323.4137)
    point P8 (250.0926, 354.5796)
    line L5 (250.0926, 354.5796) -> (250.0926, 335.146)
    circle A1 centre (250.0926, 329.6159) radius 1
    point P10 (250.0926, 329.6159)
    line L6 (243.8869, 343.1761) -> (227.099, 343.1761)
    arc A2 centre (235.4929, 343.1761) radius 8.3939 from (227.099, 343.1761) to (243.8869, 343.1761) ccw
    arc A3 centre (235.4929, 345.7885) radius 8.7911 from (243.8869, 343.1761) to (227.1407, 348.5313) ccw
    point P15 (235.4929, 354.5796)
    line L7 (222.472, 335.146) -> (219.8112, 354.5796)
    point P18 (219.8112, 354.5796)
    line L8 (219.8112, 354.5796) -> (213.1506, 335.7612)
    line L9 (213.1506, 335.7612) -> (207.2039, 354.5796)
    point P20 (207.2039, 354.5796)
    line L10 (207.2039, 354.5796) -> (203.1628, 335.146)
    construction line L11 (282.1878, 462.1713) -> (197.7035, 462.1713)
    axis line L12 (282.1878, 421.3078) -> (197.7035, 421.3078)
    construction line L13 (272.967, 451.5362) -> (272.967, 435.3975)
    line L14 (283.4709, 451.5362) -> (283.4709, 435.3975)
    line L15 (262.4631, 435.3975) -> (262.4631, 451.5362)
    arc A4 centre (272.967, 435.3975) radius 10.5039 from (283.4709, 435.3975) to (262.4631, 435.3975) cw
    arc A5 centre (272.967, 451.5362) radius 10.5039 from (262.4631, 451.5362) to (283.4709, 451.5362) cw
    point P32 (257.8927, 462.1713)
    line L16 (257.8927, 462.1713) -> (257.8927, 442.741)
    line L17 (257.8927, 442.741) -> (251.0154, 442.741)
    point P34 (251.0154, 442.741)
    arc A6 centre (251.0154, 449.6182) radius 6.8773 from (251.0154, 442.741) to (244.1382, 449.6182) cw
    line L18 (244.1382, 449.6182) -> (244.1382, 462.1713)
    point P37 (244.1382, 462.1713)
    circle A7 centre (239.2209, 442.741) radius 1
    point P38 (239.2209, 442.741)
    point P39 (238.2209, 442.741)
    line L19 (213.0066, 435.0583) -> (213.0066, 451.1969)
    arc A8 centre (223.5105, 435.0583) radius 10.5039 from (234.0144, 435.0583) to (213.0066, 435.0583) cw
    arc A9 centre (223.5105, 451.1969) radius 10.5039 from (213.0066, 451.1969) to (234.0144, 451.1969) cw
    line L20 (234.0144, 451.1969) -> (234.0144, 435.0583)
    point P46 (204.0927, 462.1713)
    line L21 (204.0927, 462.1713) -> (204.0927, 437.6926)
    arc A10 centre (193.7264, 437.6926) radius 10.3663 from (204.0927, 437.6926) to (197.7035, 428.1196) cw
    point P50 (209.9279, 442.741)
    line L22 (209.9279, 442.741) -> (197.7035, 443.1586)
    line L23 (195.8096, 442.9809) -> (183.5852, 443.3985)
    line L24 (189.9743, 462.4112) -> (189.9743, 437.9325)
    arc A11 centre (179.608, 437.9325) radius 10.3663 from (189.9743, 437.9325) to (183.5852, 428.3595) cw
    horizontal: L1 H, L2 H, L6 H, L11 H, L12 H, L17 H
    coincidence: P5 L2, P6 L1, P7 L2, P8 L1, P10 L5, A3 P15, P15 L1, P18 L1, P20 L1, P32 L8, P32 L11, P34 L8, P37 L11, P38 L17, A7 P39, P39 L17, P46 L11, P50 L17
    vertical: L5 V, L13 V, L16 V, L21 V
    tangency: A3 L1, A4 L14, A5 L14, A4 L15, A5 L15, A6 L16, A6 L17, L18 A6, A7 L3, A10 L21, L22 A7
    parallelism: L8 L4, L9 L3, L13 L14
  Pocket22: profile Sketch24, direction (0, 0, -1), length 5, thin wall 1, second thickness 1
  Sketch25 on face of Pocket2 from Sketch3.L3, origin (0, 0, 350), H (1, 0, 0), V (0, 1, 0)
    axis line L1 (-199.1708, 458.6762) -> (-288.3664, 458.6762)
    point P3 (-211.3254, 458.6762)
    line L2 (-211.3254, 458.6762) -> (-211.3254, 423.8323)
    line L3 (-211.3254, 423.8323) -> (-221.5406, 423.8323)
    arc A1 centre (-221.5406, 431.3914) radius 7.5591 from (-221.5406, 423.8323) to (-221.5406, 438.9504) cw
    line L4 (-221.5406, 438.9504) -> (-211.3254, 438.9504)
    point P8 (-211.3254, 438.9504)
    line L5 (-221.5406, 438.9504) -> (-227.9099, 458.6762)
    point P9 (-227.9099, 458.6762)
    point P10 (-237.5449, 438.9504)
    line L6 (-237.5449, 438.9504) -> (-237.5449, 455.5651)
    arc A2 centre (-240.656, 455.5651) radius 3.1111 from (-237.5449, 455.5651) to (-240.656, 458.6762) ccw
    line L7 (-240.656, 458.6762) -> (-252.1847, 458.6762)
    line L8 (-252.1847, 458.6762) -> (-252.1847, 438.9504)
    point P15 (-252.1847, 438.9504)
    point P16 (-261.8369, 438.9504)
    line L9 (-261.8369, 438.9504) -> (-261.8369, 458.6762)
    point P17 (-261.8369, 458.6762)
    line L10 (-261.8369, 438.9504) -> (-270.7656, 438.9504)
    arc A3 centre (-270.7656, 443.4012) radius 4.4508 from (-270.7656, 438.9504) to (-275.2164, 443.4012) cw
    line L11 (-275.2164, 443.4012) -> (-275.2164, 458.6762)
    point P21 (-275.2164, 458.6762)
    horizontal: L1 H, L3 H
    coincidence: P3 L1, P8 L2, P9 L1, P10 L4, P15 L4, P16 L4, P17 L1, P21 L1
    vertical: L2 V, L6 V, L8 V, L9 V
    tangency: A1 L3, L4 A1, A2 L1, A2 L6, L7 A2, L10 A1, A3 L10, L11 A3
  Pocket23: profile Sketch25, direction (0, 0, -1), length 5, thin wall 1, second thickness 1
Body2, material "Black"
  Sketch26 on face of Pocket2 from Sketch3.L3, origin (0, 0, 350), H (1, 0, 0), V (0, 1, 0)
    line L1 (-237, 720) -> (237, 720)
    line L2 (237, 720) -> (237, 562)
    line L3 (237, 562) -> (-237, 562)
    line L4 (-237, 562) -> (-237, 720)
    reference projected line E1 (320, 720) -> (-320, 720) from edge [face of Pocket2 from Sketch3.L3 | face of Pocket4]
    length L2 = 158
    distance L2 L4 = 474
    horizontal: L1 H, L3 H
    vertical: L2 V, L4 V
    coincidence: L1 E1
    symmetry: L2 L4 V
  Pad3: profile Sketch26, direction (0, 0, -1), length 30
  Sketch27 on start face of Pad3, origin (0, 0, 350), H (1, 0, 0), V (0, 1, 0)
    circle A1 centre (197.5, 680.5) radius 24.5
    point P1 (197.5, 680.5)
    reference projected line E1 (237, 562) -> (237, 720) from edge [face of Pocket2 from Sketch3.L3 | face of Pocket6 from Sketch7.L2]
    reference projected line E2 (245, 720) -> (-245, 720) from edge [end face of Pad1 | face of Pocket4]
    radius A1 = 24.5
    distance P1 E1 = 39.5
    distance P1 E2 = 39.5
  Pad4: profile Sketch27, direction (0, 0, 1), length 17.2
  RectPattern2: of Pad4, direction 1 instances 6, spacing 79, along start face of Pad3 reversed, direction 2 instances 2, spacing 79, along start face of Pad3 reversed
  Sketch28 on start face of Pad3, origin (0, 0, 350), H (1, 0, 0), V (0, 1, 0)
    point P1 (79, 720)
    line L1 (79, 720) -> (79, 562)
    point P2 (79, 562)
    reference projected line E1 (-237, 562) -> (237, 562) from edge [face of Pocket2 from Sketch3.L3 | face of Pocket6 from Sketch7.L3]
    reference projected line E2 (237, 562) -> (237, 720) from edge [face of Pocket2 from Sketch3.L3 | face of Pocket6 from Sketch7.L2]
    reference projected line E3 (245, 720) -> (-245, 720) from edge [end face of Pad1 | face of Pocket4]
    point P3 (-79, 562)
    point P4 (-79, 720)
    line L2 (-79, 720) -> (-79, 562)
    reference projected line E4 (-237, 720) -> (-237, 562) from edge [face of Pocket2 from Sketch3.L3 | face of Pocket6 from Sketch7.L4]
    reference projected line E5 (-237, 562) -> (237, 562) from edge [face of Pocket2 from Sketch3.L3 | face of Pocket6 from Sketch7.L3]
    reference projected line E6 (245, 720) -> (-245, 720) from edge [end face of Pad1 | face of Pocket4]
    distance L1 E2 = 158
    distance L2 E4 = 158
    vertical: L1 V
    coincidence: P2 E1, P1 E3, P3 E5, P4 E6
  Pocket24: profile Sketch28, direction (0, 0, -1), length 5, thin wall 1, second thickness 1
Body3, material "Plastic"
  Sketch29 on face of Pad1 from Sketch1.L4, origin (0, 0, 0), H (1, 0, 0), V (0, 0, 1)
    point P1 (320, 0)
    line L1 (320, 0) -> (-320, 0)
    line L2 (-320, 0) -> (-320, 185)
    line L3 (-320, 185) -> (320, 185)
    line L4 (320, 185) -> (320, 0)
    reference projected line E1 (-320, 185) -> (-315, 185) from edge [face of Pad1 from Sketch1.L4 | face of Pocket10]
    reference projected line E2 (320, 0) -> (320, 380) from edge [face of Pad1 from Sketch1.L1 | face of Pad1 from Sketch1.L4]
    reference projected line E3 (-320, 0) -> (-320, 380) from edge [face of Pad1 from Sketch1.L4 | face of Pad1 from Sketch1.L3]
    coincidence: P1 H, E1 L3, E2 L4, L2 E3
    horizontal: L1 H, L3 H
    vertical: L2 V, L4 V
  Pad5: profile Sketch29, direction (0, 1, 0), length 960
  Sketch30 on start face of Pad5, origin (0, 0, 0), H (1, 0, 0), V (0, 0, 1)
    point P1 (320, 30)
    line L1 (320, 30) -> (320, 0)
    point P2 (320, 0)
    line L2 (320, 0) -> (245, 0)
    point P3 (245, 0)
    line L3 (245, 0) -> (320, 30)
    reference projected line E1 (320, 0) -> (320, 185) from edge [face of Pad5 from Sketch29.L4 | start face of Pad5]
    point P4 (-320, 30)
    point P5 (-320, 0)
    point P6 (-245, 0)
    line L4 (-320, 30) -> (-320, 0)
    line L5 (-320, 0) -> (-245, 0)
    line L6 (-245, 0) -> (-320, 30)
    length L2 = 75
    length L1 = 30
    coincidence: P2 H, L1 E1
    vertical: L1 V
    horizontal: L2 H
    symmetry: P1 P4 V, P2 P5 V, P3 P6 V, L1 L4 V, L2 L5 V, L3 L6 V
  Pocket25: profile Sketch30, direction (0, 1, 0), through (limit type 6)
Body4, material "Bathroom Floor"
  Sketch31 on face of Pocket2 from Sketch3.L3, origin (0, 0, 350), H (1, 0, 0), V (0, 1, 0)
    line L1 (-160, 485) -> (-160, 385)
    arc A1 centre (0, 1660) radius 1285 from (-160, 385) to (160, 385) ccw
    point P4 (0, 375)
    line L2 (160, 385) -> (160, 485)
    arc A2 centre (0, -790) radius 1285 from (160, 485) to (-160, 485) ccw
    point P8 (0, 495)
    axis line L3 (534.9151, 435) -> (-283.043, 435)
    reference projected line E1 (-245, 320) -> (-309.2857, 320) from edge [face of Pocket2 from Sketch3.L3 | end face of Pocket3]
    length L2 = 100
    length L1 = 100
    distance L2 L1 = 320
    distance L3 E1 = 115
    distance A2 A1 = 120
    vertical: L1 V, L2 V
    coincidence: A1 P4, P4 V, A2 P8, P8 V
    symmetry: L1 L2 V, A1 A2 L3
    horizontal: L3 H
  Pad6: profile Sketch31, direction (0, 0, -1), length 30
Body5, material "Silver Grey"
  Sketch32 on face of Pocket2 from Sketch3.L3, origin (0, 0, 350), H (1, 0, 0), V (0, 1, 0)
    construction line L1 (479.259, 435) -> (35.5084, 435)
    reference projected line E1 (-245, 320) -> (-309.2857, 320) from edge [face of Pocket2 from Sketch3.L3 | end face of Pocket3]
    arc A1 centre (-240, 520) radius 162.5 from (-280, 362.5) to (-200, 362.5) ccw
    arc A2 centre (-240, 240) radius 162.5 from (-200, 397.5) to (-280, 397.5) ccw
    line L2 (-200, 362.5) -> (-200, 397.5)
    line L3 (-280, 397.5) -> (-280, 362.5)
    construction line L4 (-240, 419.4533) -> (-240, 336.2395)
    reference projected line E3 (-320, 0) -> (-320, 320) from edge [face of Pocket3 from Sketch4.L6 | face of Pad1 from Sketch1.L3]
    axis line L5 (-343.1113, 380) -> (-157.5, 380)
    point P10 (-157.5, 380)
    reference projected line E4 (-245, 320) -> (-309.2857, 320) from edge [face of Pocket2 from Sketch3.L3 | end face of Pocket3]
    distance L1 E1 = 115
    distance L3 L2 = 80
    distance A2 A1 = 45
    distance L4 E3 = 80
    length L3 = 35
    length L2 = 35
    distance L5 E4 = 60
    horizontal: L1 H, L5 H
    vertical: L4 V
    symmetry: L3 L2 L4, A2 A1 L5
    coincidence: P10 A1
  Pad7: profile Sketch32, direction (0, 0, -1), length 30, opposite side length 15
Body6, material "Black"
  Sketch33 on face of Pocket2 from Sketch3.L3, origin (0, 0, 350), H (1, 0, 0), V (0, 1, 0)
    construction line L1 (479.259, 435) -> (35.5084, 435)
    reference projected line E1 (-245, 320) -> (-309.2857, 320) from edge [face of Pocket2 from Sketch3.L3 | end face of Pocket3]
    point P7 (240, 336.2395)
    construction line L2 (152.5705, 380) -> (327.5235, 380)
    line L3 (200, 362.5) -> (200, 397.5)
    arc A1 centre (240, 240) radius 162.5 from (200, 397.5) to (280, 397.5) cw
    line L4 (280, 397.5) -> (280, 362.5)
    arc A2 centre (240, 520) radius 162.5 from (280, 362.5) to (200, 362.5) cw
    axis line L5 (240, 240) -> (240, 439.527)
    reference projected line E3 (320, 0) -> (320, 320) from edge [face of Pad1 from Sketch1.L1 | face of Pocket3 from Sketch4.L3]
    reference projected line E4 (237, 320) -> (-237, 320) from edge [face of Pad12 from Sketch38.L3 | start face of Pad12]
    distance L1 E1 = 115
    distance A1 A2 = 45
    distance L4 L3 = 80
    distance L5 E3 = 80
    distance L2 E4 = 60
    length L4 = 35
    horizontal: L1 H
    vertical: L5 V
    symmetry: L4 L3 L5, A1 A2 L2
  Pad8: profile Sketch33, direction (0, 0, -1), length 30, opposite side length 15
Body7, material "DS Green"
  Sketch34 on face of Pocket2 from Sketch3.L3, origin (0, 0, 350), H (1, 0, 0), V (0, 1, 0)
    point P5 (-240, 533.7605)
    point P6 (-327.5235, 490)
    point P7 (-240, 520)
    line L1 (-200, 507.5) -> (-200, 472.5)
    arc A1 centre (-240, 630) radius 162.5 from (-200, 472.5) to (-280, 472.5) cw
    line L2 (-280, 472.5) -> (-280, 507.5)
    arc A2 centre (-240, 350) radius 162.5 from (-280, 507.5) to (-200, 507.5) cw
    construction line L3 (-123.6268, 490) -> (-366.7796, 490)
    axis line L4 (-240, 553.4429) -> (-240, 386.3738)
    reference projected line E1 (-320, 320) -> (-320, 550) from edge [face of Pocket5 from Sketch6.L6 | face of Pad1 from Sketch1.L3]
    reference projected line E2 (-245, 550) -> (-309.2857, 550) from edge [start face of Pocket4 | face of Pocket2 from Sketch3.L3]
    distance A2 A1 = 45
    distance L2 L1 = 80
    length L2 = 35
    distance L4 E1 = 80
    distance L3 E2 = 60
    length L1 = 35
    horizontal: L3 H
    vertical: L4 V
    symmetry: L2 L1 L4, A2 A1 L3
  Pad9: profile Sketch34, direction (0, 0, -1), length 30, opposite side length 15
Body8, material "Fire Red"
  Sketch35 on face of Pocket2 from Sketch3.L3, origin (0, 0, 350), H (1, 0, 0), V (0, 1, 0)
    line L1 (200, 507.5) -> (200, 472.5)
    arc A1 centre (240, 630) radius 162.5 from (200, 472.5) to (280, 472.5) ccw
    line L2 (280, 472.5) -> (280, 507.5)
    arc A2 centre (240, 350) radius 162.5 from (280, 507.5) to (200, 507.5) ccw
    construction line L3 (152.5705, 490) -> (327.5235, 490)
    reference projected line E1 (-245, 550) -> (-309.2857, 550) from edge [start face of Pocket4 | face of Pocket2 from Sketch3.L3]
    distance L2 L1 = 80
    distance A2 A1 = 45
    distance L3 E1 = 60
    length L2 = 35
    vertical: L1 V, L2 V
    horizontal: L3 H
    symmetry: A1 A2 L3
  Pad10: profile Sketch35, direction (0, 0, -1), length 30, opposite side length 15
Body9, material "Dark Grey"
  Sketch36 on face of Pocket2 from Sketch3.L3, origin (0, 0, 350), H (1, 0, 0), V (0, 1, 0)
    point P1 (237.5, 0)
    line L1 (237.5, 0) -> (237.5, 40)
    line L2 (237.5, 40) -> (40, 40)
    line L3 (40, 40) -> (40, 80)
    line L4 (40, 80) -> (-40, 80)
    line L5 (-40, 80) -> (-40, 40)
    point P6 (-40, 40)
    line L6 (-40, 40) -> (-237.5, 40)
    line L7 (-237.5, 40) -> (-237.5, 0)
    point P8 (-237.5, 0)
    reference projected line E1 (320, 0) -> (-320, 0) from edge [face of Pad5 from Sketch29.L3 | start face of Pad5]
    line L8 (237.5, 0) -> (227.5, -3)
    point P9 (227.5, -3)
    line L9 (227.5, -3) -> (55, -3)
    line L10 (55, -3) -> (45, 0)
    point P11 (45, 0)
    line L11 (45, 0) -> (35, 0)
    point P12 (35, 0)
    line L12 (35, 0) -> (25, -3)
    point P13 (25, -3)
    line L13 (25, -3) -> (-25, -3)
    line L14 (-25, -3) -> (-35, 0)
    point P15 (-35, 0)
    line L15 (-35, 0) -> (-45, 0)
    line L16 (-45, 0) -> (-55, -3)
    point P17 (-55, -3)
    line L17 (-55, -3) -> (-227.5, -3)
    point P18 (-227.5, -3)
    line L18 (-227.5, -3) -> (-237.5, 0)
    reference projected line E2 (245, 0) -> (320, 0) from edge [face of Pad1 from Sketch1.L4 | face of Pocket3 from Sketch4.L3]
    distance L3 L5 = 80
    distance L1 L7 = 475
    distance L2 E1 = 40
    distance L4 H = 80
    distance E2 L9 = 3
    length L13 = 50
    length L11 = 10
    distance P12 V = 35
    distance P9 L1 = 10
    distance P18 L7 = 10
    coincidence: P1 H, P6 L2, P8 H, P11 H, P13 L9, P15 L11, P17 L9
    vertical: L1 V, L3 V, L5 V, L7 V
    horizontal: L2 H, L4 H, L6 H, L9 H, L11 H, L13 H, L15 H, L17 H
    symmetry: L3 L5 V, L1 L7 V, L14 L12 V, L11 L15 V, L10 L16 V
    parallelism: L16 L12, L13 L9, L9 L17
  Pad11: profile Sketch36, direction (0, 0, -1), length 150, opposite side length 5
  Sketch37 on face of Pad11 from Sketch36.L17, origin (0, -3, 0), H (1, 0, 0), V (0, 0, 1)
    point P1 (0, 365)
    line L1 (0, 365) -> (237.5, 365)
    point P2 (237.5, 365)
    line L2 (237.5, 365) -> (237.5, 345)
    point P3 (237.5, 345)
    line L3 (237.5, 345) -> (227.5, 355)
    point P4 (227.5, 355)
    line L4 (227.5, 355) -> (55, 355)
    point P5 (55, 355)
    line L5 (55, 355) -> (45, 345)
    point P6 (45, 345)
    line L6 (45, 345) -> (35, 345)
    point P7 (35, 345)
    line L7 (35, 345) -> (25, 355)
    point P8 (25, 355)
    line L8 (25, 355) -> (0, 355)
    point P9 (0, 355)
    reference projected line E1 (-25, 355) -> (25, 355) from edge [face of Pad11 from Sketch36.L13 | start face of Pad11]
    reference projected line E2 (45, 355) -> (45, 200) from edge [face of Pad11 from Sketch36.L11 | face of Pad11 from Sketch36.L10]
    reference projected line E3 (55, 355) -> (55, 200) from edge [face of Pad11 from Sketch36.L10 | face of Pad11 from Sketch36.L9]
    reference projected line E4 (35, 355) -> (35, 200) from edge [face of Pad11 from Sketch36.L12 | face of Pad11 from Sketch36.L11]
    reference projected line E5 (25, 355) -> (25, 200) from edge [face of Pad11 from Sketch36.L13 | face of Pad11 from Sketch36.L12]
    reference projected line E6 (227.5, 355) -> (227.5, 200) from edge [face of Pad11 from Sketch36.L9 | face of Pad11 from Sketch36.L8]
    reference projected line E7 (237.5, 350) -> (237.5, 195) from edge [face of Pocket14 from Sketch15.L1 | face of Pad1 from Sketch1.L4]
    point P10 (0, 365)
    point P11 (-237.5, 365)
    point P12 (-237.5, 345)
    point P13 (-227.5, 355)
    point P14 (-55, 355)
    point P15 (-45, 345)
    point P16 (-35, 345)
    point P17 (-25, 355)
    point P18 (0, 355)
    line L9 (0, 365) -> (-237.5, 365)
    line L10 (-237.5, 365) -> (-237.5, 345)
    line L11 (-237.5, 345) -> (-227.5, 355)
    line L12 (-227.5, 355) -> (-55, 355)
    line L13 (-55, 355) -> (-45, 345)
    line L14 (-45, 345) -> (-35, 345)
    line L15 (-35, 345) -> (-25, 355)
    line L16 (-25, 355) -> (0, 355)
    distance L6 L8 = 10
    distance L1 L4 = 10
    coincidence: P1 V, P8 L4, P9 V, E1 L8, P6 E2, P5 E3, P7 E4, P8 E5, P4 E6, L2 E7, P1 P10, P9 P18
    horizontal: L1 H, L4 H, L6 H, L8 H
    vertical: L2 V
    parallelism: L7 L3, L4 L8
    symmetry: P1 P10 V, P2 P11 V, P3 P12 V, P4 P13 V, P5 P14 V, P6 P15 V, P7 P16 V, P8 P17 V, P9 P18 V, L1 L9 V, L2 L10 V, L3 L11 V, L4 L12 V, L5 L13 V, L6 L14 V, L7 L15 V, L8 L16 V
  Pocket26: profile Sketch37, direction (0, 1, 0), length 80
